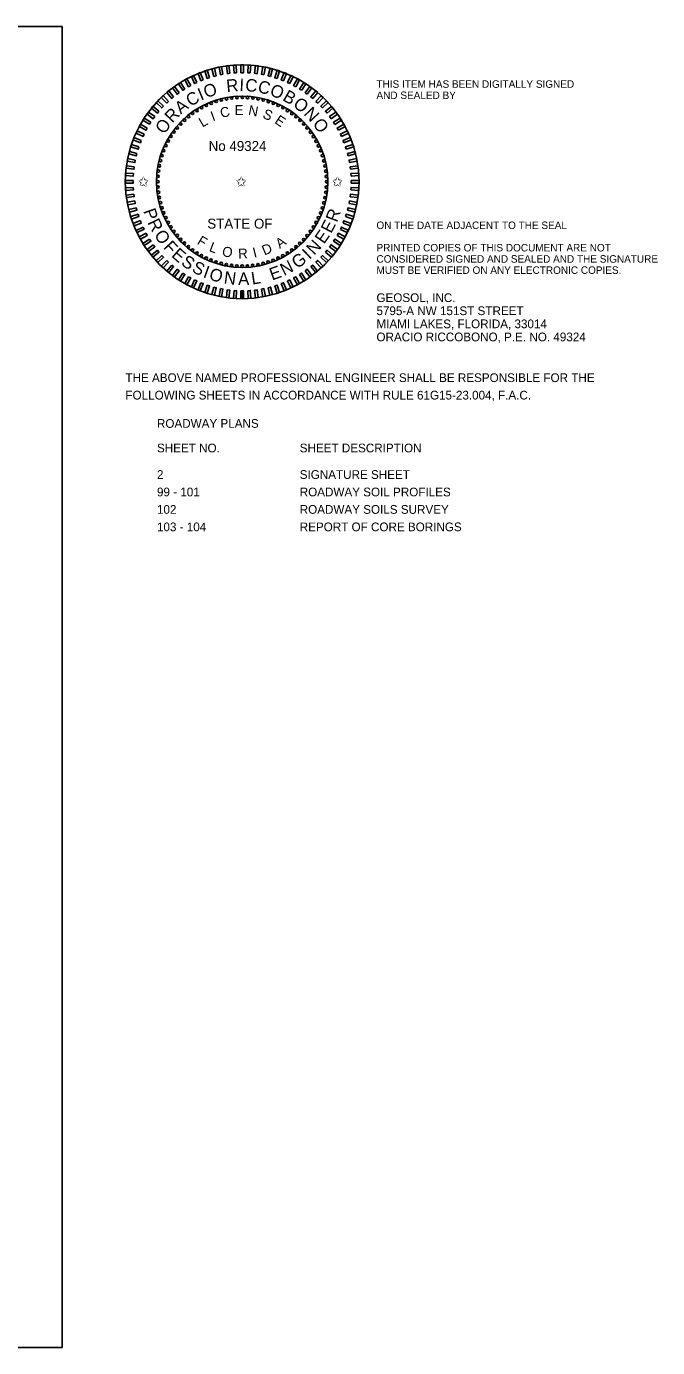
# Model space of a CAD drawing. Extents: x -816.9 to -790.1, y -2199.5 to -2188.9.
# Drawn here: x -795.12 to -790.06, y -2199.5 to -2188.9 of the extents above; entities that cross this region are included whole.
import ezdxf

# ---------------------------------------------------------------- set-up
doc = ezdxf.new("R2010")
doc.units = 0
for name, color, linetype in [('Logo_dp', 7, 'Continuous'), ('NonPlottingEle_dp', 7, 'Continuous'), ('PlotBorder_dp', 7, 'Continuous'), ('TextMisc', 7, 'Continuous'), ('TextNotes', 7, 'Continuous')]:
    doc.layers.add(name, color=color, linetype=linetype)

msp = doc.modelspace()

# ---------------------------------------------------------------- linework, layer by layer
at = {"layer": 'Logo_dp'}
for p, q in [((-793.4, -2191.084), (-793.4, -2191.022)), ((-793.39, -2191.084), (-793.39, -2191.022)), ((-793.38, -2191.084), (-793.38, -2191.022))]:
    msp.add_line(p, q, dxfattribs=at)
for points in [[(-793.489, -2189.277), (-793.509, -2189.28), (-793.517, -2189.218), (-793.497, -2189.215)], [(-793.435, -2189.273), (-793.455, -2189.274), (-793.459, -2189.212), (-793.439, -2189.211)], [(-793.38, -2189.272), (-793.4, -2189.272), (-793.4, -2189.209), (-793.38, -2189.209)], [(-793.325, -2189.274), (-793.345, -2189.273), (-793.341, -2189.211), (-793.321, -2189.212)], [(-793.27, -2189.28), (-793.29, -2189.277), (-793.282, -2189.215), (-793.262, -2189.218)], [(-793.803, -2189.375), (-793.82, -2189.385), (-793.85, -2189.33), (-793.833, -2189.32)], [(-793.753, -2189.351), (-793.772, -2189.359), (-793.798, -2189.303), (-793.78, -2189.294)], [(-793.703, -2189.329), (-793.721, -2189.337), (-793.744, -2189.279), (-793.726, -2189.271)], [(-793.651, -2189.311), (-793.67, -2189.318), (-793.689, -2189.258), (-793.67, -2189.252)], [(-793.598, -2189.297), (-793.617, -2189.302), (-793.633, -2189.241), (-793.613, -2189.236)], [(-793.544, -2189.285), (-793.564, -2189.289), (-793.575, -2189.228), (-793.556, -2189.224)], [(-793.216, -2189.289), (-793.236, -2189.285), (-793.224, -2189.224), (-793.204, -2189.228)], [(-793.162, -2189.302), (-793.182, -2189.297), (-793.166, -2189.236), (-793.147, -2189.241)], [(-793.11, -2189.318), (-793.129, -2189.312), (-793.11, -2189.252), (-793.091, -2189.258)], [(-793.058, -2189.337), (-793.077, -2189.33), (-793.054, -2189.271), (-793.035, -2189.279)], [(-793.008, -2189.359), (-793.026, -2189.351), (-793, -2189.294), (-792.982, -2189.303)], [(-792.959, -2189.385), (-792.977, -2189.375), (-792.947, -2189.32), (-792.929, -2189.33)], [(-793.94, -2189.466), (-793.955, -2189.479), (-793.995, -2189.431), (-793.98, -2189.418)], [(-793.896, -2189.433), (-793.912, -2189.445), (-793.949, -2189.394), (-793.933, -2189.382)], [(-793.85, -2189.403), (-793.867, -2189.413), (-793.901, -2189.361), (-793.884, -2189.35)], [(-792.912, -2189.413), (-792.929, -2189.403), (-792.896, -2189.35), (-792.879, -2189.361)], [(-792.867, -2189.445), (-792.884, -2189.433), (-792.847, -2189.383), (-792.831, -2189.394)], [(-792.824, -2189.479), (-792.84, -2189.466), (-792.8, -2189.418), (-792.784, -2189.431)], [(-794.021, -2189.54), (-794.035, -2189.555), (-794.08, -2189.512), (-794.066, -2189.498)], [(-793.981, -2189.502), (-793.996, -2189.516), (-794.039, -2189.47), (-794.024, -2189.456)], [(-792.783, -2189.516), (-792.798, -2189.502), (-792.755, -2189.457), (-792.741, -2189.47)], [(-792.745, -2189.555), (-792.759, -2189.541), (-792.713, -2189.498), (-792.7, -2189.512)], [(-794.123, -2189.669), (-794.134, -2189.686), (-794.187, -2189.653), (-794.176, -2189.636)], [(-794.092, -2189.624), (-794.104, -2189.641), (-794.154, -2189.604), (-794.142, -2189.588)], [(-794.058, -2189.581), (-794.07, -2189.597), (-794.119, -2189.557), (-794.106, -2189.541)], [(-792.709, -2189.597), (-792.722, -2189.581), (-792.674, -2189.542), (-792.661, -2189.557)], [(-792.676, -2189.641), (-792.688, -2189.624), (-792.637, -2189.588), (-792.625, -2189.604)], [(-792.646, -2189.687), (-792.656, -2189.67), (-792.604, -2189.636), (-792.593, -2189.653)], [(-794.177, -2189.765), (-794.186, -2189.783), (-794.242, -2189.757), (-794.234, -2189.738)], [(-794.152, -2189.716), (-794.161, -2189.734), (-794.216, -2189.704), (-794.206, -2189.686)], [(-792.618, -2189.734), (-792.628, -2189.716), (-792.573, -2189.686), (-792.563, -2189.704)], [(-792.594, -2189.783), (-792.602, -2189.765), (-792.546, -2189.739), (-792.537, -2189.757)], [(-794.219, -2189.867), (-794.225, -2189.886), (-794.285, -2189.867), (-794.278, -2189.847)], [(-794.2, -2189.815), (-794.207, -2189.834), (-794.265, -2189.811), (-794.258, -2189.792)], [(-792.573, -2189.834), (-792.58, -2189.815), (-792.522, -2189.792), (-792.514, -2189.811)], [(-792.555, -2189.886), (-792.561, -2189.867), (-792.501, -2189.848), (-792.495, -2189.867)], [(-794.235, -2189.919), (-794.24, -2189.939), (-794.3, -2189.923), (-794.295, -2189.904)], [(-792.54, -2189.939), (-792.545, -2189.92), (-792.484, -2189.904), (-792.479, -2189.924)], [(-794.257, -2190.027), (-794.259, -2190.047), (-794.321, -2190.039), (-794.319, -2190.019)], [(-794.248, -2189.973), (-794.251, -2189.993), (-794.313, -2189.981), (-794.309, -2189.961)], [(-792.528, -2189.993), (-792.532, -2189.973), (-792.471, -2189.961), (-792.467, -2189.981)], [(-792.52, -2190.047), (-792.523, -2190.027), (-792.461, -2190.019), (-792.459, -2190.039)], [(-794.265, -2190.137), (-794.265, -2190.157), (-794.327, -2190.157), (-794.327, -2190.137)], [(-794.263, -2190.082), (-794.264, -2190.102), (-794.326, -2190.098), (-794.325, -2190.078)], [(-792.516, -2190.102), (-792.517, -2190.082), (-792.455, -2190.078), (-792.454, -2190.098)], [(-792.515, -2190.157), (-792.515, -2190.137), (-792.452, -2190.137), (-792.452, -2190.157)], [(-794.264, -2190.192), (-794.263, -2190.212), (-794.325, -2190.216), (-794.326, -2190.196)], [(-794.259, -2190.246), (-794.257, -2190.266), (-794.319, -2190.274), (-794.321, -2190.254)], [(-792.523, -2190.267), (-792.521, -2190.247), (-792.459, -2190.254), (-792.461, -2190.274)], [(-792.517, -2190.212), (-792.516, -2190.192), (-792.454, -2190.196), (-792.455, -2190.216)], [(-794.251, -2190.301), (-794.248, -2190.321), (-794.309, -2190.332), (-794.313, -2190.312)], [(-794.24, -2190.355), (-794.235, -2190.374), (-794.295, -2190.39), (-794.3, -2190.37)], [(-792.545, -2190.374), (-792.54, -2190.355), (-792.479, -2190.37), (-792.484, -2190.39)], [(-792.532, -2190.321), (-792.528, -2190.301), (-792.467, -2190.313), (-792.471, -2190.332)], [(-794.225, -2190.408), (-794.219, -2190.427), (-794.278, -2190.446), (-794.285, -2190.427)], [(-794.207, -2190.459), (-794.2, -2190.478), (-794.258, -2190.501), (-794.265, -2190.482)], [(-792.58, -2190.478), (-792.573, -2190.46), (-792.515, -2190.483), (-792.522, -2190.501)], [(-792.561, -2190.427), (-792.555, -2190.408), (-792.495, -2190.427), (-792.501, -2190.446)], [(-794.186, -2190.51), (-794.177, -2190.528), (-794.234, -2190.555), (-794.242, -2190.537)], [(-794.162, -2190.559), (-794.152, -2190.577), (-794.207, -2190.607), (-794.216, -2190.59)], [(-792.628, -2190.577), (-792.618, -2190.56), (-792.564, -2190.59), (-792.573, -2190.607)], [(-792.602, -2190.529), (-792.594, -2190.51), (-792.537, -2190.537), (-792.546, -2190.555)], [(-794.134, -2190.607), (-794.123, -2190.624), (-794.176, -2190.658), (-794.187, -2190.641)], [(-794.104, -2190.653), (-794.092, -2190.669), (-794.142, -2190.706), (-794.154, -2190.69)], [(-794.071, -2190.697), (-794.058, -2190.712), (-794.106, -2190.752), (-794.119, -2190.737)], [(-792.722, -2190.712), (-792.709, -2190.697), (-792.661, -2190.737), (-792.674, -2190.752)], [(-792.688, -2190.669), (-792.676, -2190.653), (-792.626, -2190.69), (-792.637, -2190.706)], [(-792.657, -2190.624), (-792.646, -2190.607), (-792.593, -2190.641), (-792.604, -2190.658)], [(-794.035, -2190.738), (-794.021, -2190.753), (-794.066, -2190.796), (-794.08, -2190.781)], [(-793.996, -2190.778), (-793.982, -2190.792), (-794.024, -2190.837), (-794.039, -2190.823)], [(-792.798, -2190.792), (-792.784, -2190.778), (-792.741, -2190.823), (-792.756, -2190.837)], [(-792.759, -2190.753), (-792.745, -2190.739), (-792.7, -2190.781), (-792.713, -2190.796)], [(-793.956, -2190.815), (-793.94, -2190.827), (-793.98, -2190.876), (-793.995, -2190.863)], [(-793.912, -2190.849), (-793.896, -2190.861), (-793.933, -2190.911), (-793.949, -2190.899)], [(-793.867, -2190.88), (-793.85, -2190.891), (-793.884, -2190.944), (-793.901, -2190.933)], [(-793.82, -2190.909), (-793.803, -2190.918), (-793.833, -2190.973), (-793.85, -2190.963)], [(-792.977, -2190.919), (-792.96, -2190.909), (-792.929, -2190.964), (-792.947, -2190.973)], [(-792.93, -2190.891), (-792.913, -2190.88), (-792.879, -2190.933), (-792.896, -2190.944)], [(-792.884, -2190.861), (-792.867, -2190.849), (-792.831, -2190.899), (-792.847, -2190.911)], [(-792.84, -2190.828), (-792.824, -2190.815), (-792.785, -2190.863), (-792.8, -2190.876)], [(-793.772, -2190.934), (-793.753, -2190.943), (-793.78, -2190.999), (-793.798, -2190.991)], [(-793.721, -2190.957), (-793.703, -2190.964), (-793.726, -2191.022), (-793.744, -2191.015)], [(-793.67, -2190.976), (-793.651, -2190.982), (-793.67, -2191.041), (-793.689, -2191.035)], [(-793.617, -2190.992), (-793.598, -2190.997), (-793.613, -2191.057), (-793.633, -2191.052)], [(-793.564, -2191.004), (-793.544, -2191.008), (-793.556, -2191.07), (-793.576, -2191.066)], [(-793.51, -2191.014), (-793.49, -2191.016), (-793.497, -2191.078), (-793.517, -2191.076)], [(-793.455, -2191.019), (-793.435, -2191.021), (-793.439, -2191.083), (-793.459, -2191.082)], [(-793.345, -2191.021), (-793.325, -2191.019), (-793.321, -2191.082), (-793.341, -2191.083)], [(-793.29, -2191.016), (-793.27, -2191.014), (-793.262, -2191.076), (-793.282, -2191.078)], [(-793.236, -2191.008), (-793.216, -2191.004), (-793.204, -2191.066), (-793.224, -2191.07)], [(-793.182, -2190.997), (-793.163, -2190.992), (-793.147, -2191.052), (-793.167, -2191.057)], [(-793.129, -2190.982), (-793.11, -2190.976), (-793.091, -2191.035), (-793.11, -2191.042)], [(-793.077, -2190.964), (-793.058, -2190.957), (-793.035, -2191.015), (-793.054, -2191.022)], [(-793.027, -2190.943), (-793.008, -2190.934), (-792.982, -2190.991), (-793, -2190.999)], [(-793.4, -2191.022), (-793.38, -2191.022), (-793.38, -2191.084), (-793.4, -2191.084)]]:
    msp.add_lwpolyline(points, close=True, dxfattribs=at)
for centre in [(-793.678, -2189.534), (-793.639, -2189.517), (-793.599, -2189.502), (-793.558, -2189.49), (-793.516, -2189.481), (-793.474, -2189.475), (-793.432, -2189.471), (-793.389, -2189.469), (-793.347, -2189.471), (-793.304, -2189.475), (-793.262, -2189.481), (-793.221, -2189.491), (-793.18, -2189.503), (-793.14, -2189.517), (-793.101, -2189.534), (-793.821, -2189.624), (-793.788, -2189.598), (-793.752, -2189.575), (-793.716, -2189.553), (-793.063, -2189.553), (-793.026, -2189.575), (-792.991, -2189.599), (-792.958, -2189.625), (-793.938, -2189.748), (-793.912, -2189.715), (-793.883, -2189.683), (-793.853, -2189.653), (-792.926, -2189.653), (-792.896, -2189.683), (-792.868, -2189.715), (-792.841, -2189.749), (-794.003, -2189.858), (-793.983, -2189.82), (-793.962, -2189.783), (-792.818, -2189.784), (-792.796, -2189.821), (-792.777, -2189.859), (-794.034, -2189.937), (-794.02, -2189.897), (-792.76, -2189.898), (-792.745, -2189.938), (-794.062, -2190.061), (-794.055, -2190.019), (-794.046, -2189.978), (-792.734, -2189.979), (-792.724, -2190.02), (-792.718, -2190.062), (-794.067, -2190.146), (-794.066, -2190.104), (-792.714, -2190.105), (-792.712, -2190.147), (-794.066, -2190.189), (-794.062, -2190.231), (-794.055, -2190.273), (-792.725, -2190.274), (-792.718, -2190.232), (-792.714, -2190.19), (-794.046, -2190.315), (-794.034, -2190.356), (-792.746, -2190.357), (-792.734, -2190.316), (-794.02, -2190.396), (-794.003, -2190.435), (-793.984, -2190.473), (-792.796, -2190.474), (-792.777, -2190.436), (-792.76, -2190.397), (-793.962, -2190.509), (-793.938, -2190.545), (-793.912, -2190.578), (-792.868, -2190.579), (-792.842, -2190.545), (-792.818, -2190.51), (-793.884, -2190.61), (-793.854, -2190.64), (-793.822, -2190.668), (-793.789, -2190.695), (-792.992, -2190.695), (-792.958, -2190.669), (-792.927, -2190.641), (-792.896, -2190.611), (-793.753, -2190.719), (-793.717, -2190.74), (-793.679, -2190.76), (-793.64, -2190.776), (-793.6, -2190.791), (-793.559, -2190.803), (-793.517, -2190.812), (-793.263, -2190.812), (-793.222, -2190.803), (-793.181, -2190.791), (-793.141, -2190.777), (-793.102, -2190.76), (-793.064, -2190.741), (-793.027, -2190.719), (-793.475, -2190.819), (-793.433, -2190.823), (-793.39, -2190.824), (-793.348, -2190.823), (-793.306, -2190.819)]:
    msp.add_circle(centre, 0.01, dxfattribs=at)
at = {"layer": 'NonPlottingEle_dp'}
for radius in [0.938, 0.688]:
    msp.add_circle((-793.39, -2190.147), radius, dxfattribs=at)
at = {"layer": 'PlotBorder_dp'}
msp.add_lwpolyline([(-811.336, -2199.501), (-794.836, -2199.501), (-794.836, -2188.901), (-811.336, -2188.901)], close=True, dxfattribs=at)

# ---------------------------------------------------------------- texts
at = {"layer": 'Logo_dp'}
for s, height, rotation, p in [('R', 0.1, 5.3723, (-793.513, -2189.428)), ('I', 0.1, 357.5509, (-793.414, -2189.418)), ('C', 0.1, 354.0177, (-793.369, -2189.418)), ('C', 0.1, 30.3825, (-793.805, -2189.547)), ('I', 0.1, 22.6457, (-793.721, -2189.497)), ('O', 0.1, 19.1125, (-793.68, -2189.477)), ('C', 0.1, 346.2809, (-793.271, -2189.427)), ('O', 0.1, 338.5441, (-793.175, -2189.45)), ('B', 0.1, 329.8833, (-793.072, -2189.49)), ('A', 0.1, 38.1495, (-793.883, -2189.609)), ('E', 0.08, 0.4186, (-793.45, -2189.612)), ('N', 0.08, 349.2914, (-793.345, -2189.61)), ('O', 0.1, 322.2793, (-792.988, -2189.538)), ('R', 0.1, 45.9708, (-793.951, -2189.681)), ('L', 0.08, 30.4021, (-793.709, -2189.713)), ('I', 0.08, 20.0117, (-793.626, -2189.663)), ('C', 0.08, 12.2025, (-793.558, -2189.635)), ('S', 0.08, 337.0221, (-793.232, -2189.632)), ('E', 0.08, 325.8663, (-793.136, -2189.672)), ('N', 0.1, 313.6185, (-792.901, -2189.605)), ('O', 0.1, 54.6317, (-794.015, -2189.771)), ('O', 0.1, 305.3683, (-792.828, -2189.681)), ('P', 0.1, 289.4055, (-794.185, -2190.381)), ('R', 0.1, 69.5134, (-792.63, -2190.477)), ('R', 0.1, 296.1458, (-794.152, -2190.473)), ('E', 0.1, 62.4712, (-792.676, -2190.567)), ('O', 0.1, 303.9671, (-794.1, -2190.574)), ('F', 0.08, 328.7241, (-793.758, -2190.643)), ('E', 0.1, 55.4289, (-792.733, -2190.652)), ('F', 0.1, 312.628, (-794.028, -2190.676)), ('E', 0.1, 319.0783, (-793.964, -2190.744)), ('L', 0.08, 339.2916, (-793.661, -2190.702)), ('O', 0.08, 349.6821, (-793.556, -2190.742)), ('R', 0.08, 2.3398, (-793.421, -2190.764)), ('I', 0.08, 14.2037, (-793.294, -2190.757)), ('D', 0.08, 22.0128, (-793.212, -2190.739)), ('A', 0.08, 34.4992, (-793.088, -2190.686)), ('I', 0.1, 43.6456, (-792.85, -2190.775)), ('N', 0.1, 47.1788, (-792.812, -2190.741)), ('S', 0.1, 326.1206, (-793.887, -2190.81)), ('S', 0.1, 333.193, (-793.801, -2190.866)), ('N', 0.1, 26.8614, (-793.054, -2190.904)), ('G', 0.1, 35.1115, (-792.949, -2190.848)), ('I', 0.1, 340.2654, (-793.71, -2190.911)), ('O', 0.1, 343.7986, (-793.662, -2190.93)), ('N', 0.1, 352.4595, (-793.541, -2190.962)), ('A', 0.1, 0.7097, (-793.422, -2190.975)), ('L', 0.1, 8.4767, (-793.31, -2190.972)), ('E', 0.1, 19.8191, (-793.15, -2190.94))]:
    msp.add_text(s, height=height, rotation=rotation, dxfattribs=at).set_placement(p)
for s, p in [('No 49324', (-793.659, -2189.9)), ('✩', (-794.225, -2190.185)), ('✩', (-793.44, -2190.185)), ('✩', (-792.668, -2190.185)), ('STATE OF', (-793.67, -2190.523))]:
    msp.add_text(s, height=0.08, dxfattribs=at).set_placement(p)
at = {"layer": 'TextMisc'}
for s, height, p in [('AND SEALED BY', 0.06, (-792.312, -2189.483)), ('THIS ITEM HAS BEEN DIGITALLY SIGNED ', 0.06, (-792.312, -2189.393)), ('ON THE DATE ADJACENT TO THE SEAL', 0.06, (-792.312, -2190.526)), ('PRINTED COPIES OF THIS DOCUMENT ARE NOT ', 0.06, (-792.312, -2190.706)), ('CONSIDERED SIGNED AND SEALED AND THE SIGNATURE ', 0.06, (-792.312, -2190.796)), ('MUST BE VERIFIED ON ANY ELECTRONIC COPIES.', 0.06, (-792.312, -2190.886)), ('GEOSOL, INC.', 0.07, (-792.312, -2191.112)), ('5795-A NW 151ST STREET', 0.07, (-792.312, -2191.217)), ('MIAMI LAKES, FLORIDA, 33014', 0.07, (-792.312, -2191.322)), ('ORACIO RICCOBONO, P.E. NO. 49324', 0.07, (-792.312, -2191.427)), ('THE ABOVE NAMED PROFESSIONAL ENGINEER SHALL BE RESPONSIBLE FOR THE ', 0.07, (-794.327, -2191.754)), ('FOLLOWING SHEETS IN ACCORDANCE WITH RULE 61G15-23.004, F.A.C.', 0.07, (-794.327, -2191.894)), ('ROADWAY PLANS', 0.07, (-794.074, -2192.121))]:
    msp.add_text(s, height=height, dxfattribs=at).set_placement(p)
at = {"layer": 'TextNotes'}
for s, p in [('SHEET NO.', (-794.074, -2192.318)), ('SHEET DESCRIPTION', (-792.928, -2192.318)), ('2', (-794.074, -2192.531)), ('SIGNATURE SHEET', (-792.928, -2192.531)), ('99 - 101', (-794.074, -2192.671)), ('ROADWAY SOIL PROFILES', (-792.928, -2192.671)), ('102', (-794.074, -2192.811)), ('ROADWAY SOILS SURVEY', (-792.928, -2192.811)), ('103 - 104', (-794.074, -2192.951)), ('REPORT OF CORE BORINGS', (-792.928, -2192.951))]:
    msp.add_text(s, height=0.07, dxfattribs=at).set_placement(p)

doc.saveas('drawing.dxf')
